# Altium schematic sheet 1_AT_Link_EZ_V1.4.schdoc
size 309 x 223 mm; Symbol: Artery_A4; Device: Artery_A4; Company: Artery Technology; Drawed: SD; Version: 1.0; Page Size: A4; @Project Name: AT-START-A403A V1.3; @Page Count: 5; @Update Date: 2023-11-22; @Schematic Name: AT_START_A403A; @Page No: 1; @Page Name: AT_Link_EZ_V1.4
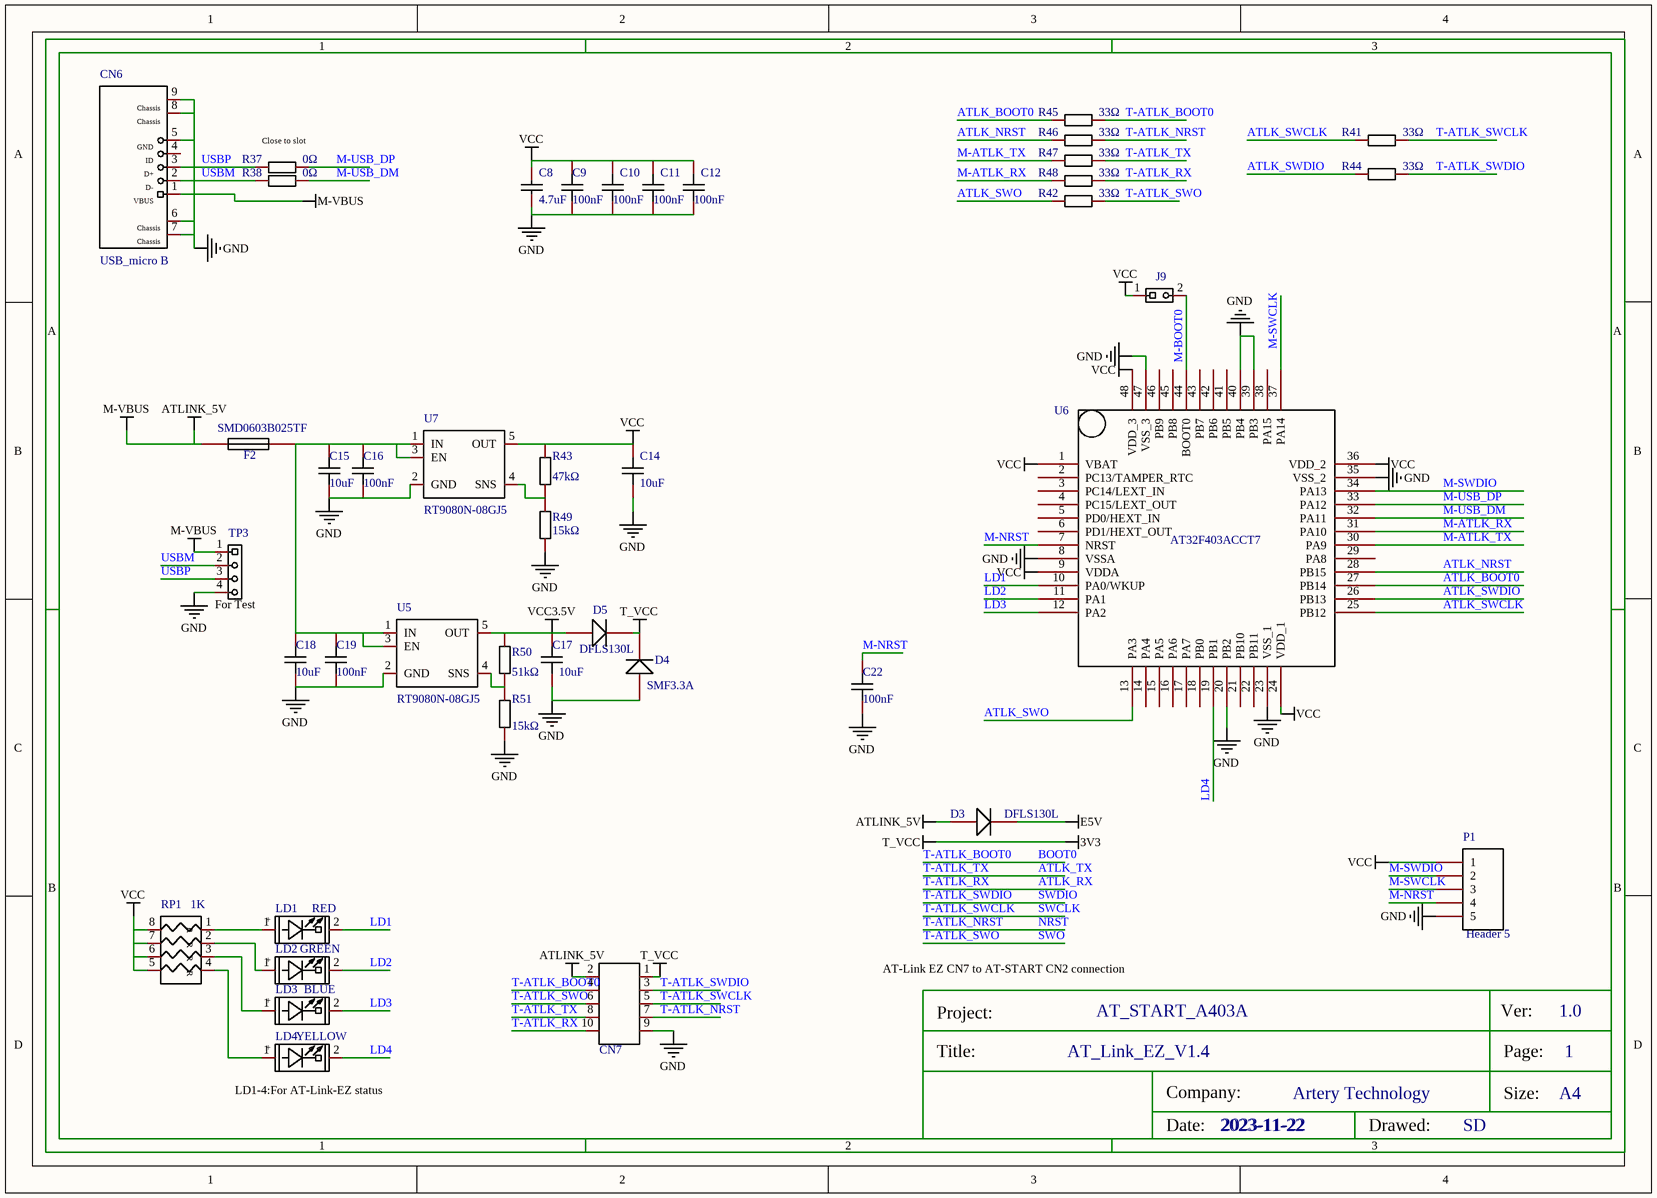
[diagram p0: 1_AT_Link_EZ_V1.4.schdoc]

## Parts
C8  value 4.7uF  [C0603]  (hidden comment: CL10A475KO8NNNC)
C9  value 100nF  [C0603]  (hidden comment: CC0603KRX7R9BB104)
C10  value 100nF  [C0603]  (hidden comment: CC0603KRX7R9BB104)
C11  value 100nF  [C0603]  (hidden comment: CC0603KRX7R9BB104)
C12  value 100nF  [C0603]  (hidden comment: CC0603KRX7R9BB104)
C14  value 10uF  [C0603]  (hidden comment: CL10A106MA8NRNC)
C15  value 10uF  [C0603]  (hidden comment: CL10A106MA8NRNC)
C16  value 100nF  [C0603]  (hidden comment: CC0603KRX7R9BB104)
C17  value 10uF  [C0603]  (hidden comment: CL10A106MA8NRNC)
C18  value 10uF  [C0603]  (hidden comment: CL10A106MA8NRNC)
C19  value 100nF  [C0603]  (hidden comment: CC0603KRX7R9BB104)
C22  value 100nF  [C0603]  (hidden comment: CC0603KRX7R9BB104)
CN6  USB_micro B  [USB_MIC_DIP]
CN7  CON1  [HDR2X5]  (value not drawn)
D3  DFLS130L  [SOD-123]
D4  SMF3.3A  [SOD-123]
D5  DFLS130L  [SOD-123]
F2  SMD0603B025TF  [R0603]
J9  1X2P_2.54M  [HDR1X2]  (value not drawn)
LD1  RED  [LED0603]
LD2  GREEN  [LED0603]
LD3  BLUE  [LED0603]
LD4  YELLOW  [LED0603]
P1  Header 5  [HDR1X5]
R37  0Ω  [R0603]
R38  0Ω  [R0603]
R41  value 33Ω  [R0603]  (hidden comment: 0603WAF330JT5E)
R42  value 33Ω  [R0603]  (hidden comment: 0603WAF330JT5E)
R43  value 47kΩ  [R0603]  (hidden comment: 0603WAF4702T5E)
R44  value 33Ω  [R0603]  (hidden comment: 0603WAF330JT5E)
R45  value 33Ω  [R0603]  (hidden comment: 0603WAF330JT5E)
R46  value 33Ω  [R0603]  (hidden comment: 0603WAF330JT5E)
R47  value 33Ω  [R0603]  (hidden comment: 0603WAF330JT5E)
R48  value 33Ω  [R0603]  (hidden comment: 0603WAF330JT5E)
R49  value 15kΩ  [R0603]  (hidden comment: 0603WAF1502T5E)
R50  value 51kΩ  [R0603]  (hidden comment: 0603WAF5102T5E)
R51  value 15kΩ  [R0603]  (hidden comment: 0603WAF1502T5E)
RP1  1K  [RP_4-0603]
TP3  1X4P_2.54F  [HDR1X4 - TOP]  (value not drawn)
U5  RT9080N-08GJ5  [SOT-23-5]
U6  AT32F403ACCT7  [LQFP-48_L7.0-W7.0-P0.50-LS9.0-BL]
U7  RT9080N-08GJ5  [SOT-23-5]

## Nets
3V3: CN7.1 D4.2(K) D5.2(K)  [also labelled T_VCC]
ATLINK_5V: CN6.1(VBUS) CN7.2 D3.1(A) F2.1 TP3.1  [also labelled M-VBUS]
E5V: D3.2(K)
GND: C8.1 C9.1 C10.1 C11.1 C12.1 C14.1 C15.1 C16.1 C17.1 C18.1 C19.1 C22.1 CN6.5(GND) CN6.6 CN6.7 CN6.8 CN6.9 CN7.9 D4.1(A) P1.5 R49.2 R51.2 TP3.4 U5.2(GND) U6.8(VSSA) U6.20(PB2) U6.23(VSS_1) U6.35(VSS_2) U6.39(PB3) U6.40(PB4) U6.47(VSS_3) U7.2(GND)
VCC: C8.2 C9.2 C10.2 C11.2 C12.2 C14.2 J9.1 P1.1 R43.1 RP1.5 RP1.6 RP1.7 RP1.8 U6.1(VBAT) U6.9(VDDA) U6.24(VDD_1) U6.36(VDD_2) U6.48(VDD_3) U7.5(OUT)
VCC3.5V: C17.2 D5.1(A) R50.1 U5.5(OUT)
ATLK_BOOT0: R45.1 U6.27(PB14)
ATLK_NRST: R46.1 U6.28(PB15)
ATLK_RX: CN7.10 R48.2  [also labelled T-ATLK_RX]
ATLK_SWCLK: R41.1 U6.25(PB12)
ATLK_SWDIO: R44.1 U6.26(PB13)
ATLK_SWO: R42.1 U6.13(PA3)
ATLK_TX: CN7.8 R47.2  [also labelled T-ATLK_TX]
BOOT0: CN7.4 R45.2  [also labelled T-ATLK_BOOT0]
LD1: LD1.2(CATHODE) U6.10(PA0/WKUP)
LD2: LD2.2(CATHODE) U6.11(PA1)
LD3: LD3.2(CATHODE) U6.12(PA2)
LD4: LD4.2(CATHODE) U6.19(PB1)
M-ATLK_RX: R48.1 U6.31(PA10)
M-ATLK_TX: R47.1 U6.30(PA9)
M-BOOT0: J9.2 U6.44(BOOT0)
M-NRST: C22.2 P1.4 U6.7(NRST)
M-SWCLK: P1.3 U6.37(PA14)
M-SWDIO: P1.2 U6.34(PA13)
M-USB_DM: R38.1 U6.32(PA11)
M-USB_DP: R37.1 U6.33(PA12)
NRST: CN7.7 R46.2  [also labelled T-ATLK_NRST]
SWCLK: CN7.5 R41.2  [also labelled T-ATLK_SWCLK]
SWDIO: CN7.3 R44.2  [also labelled T-ATLK_SWDIO]
SWO: CN7.6 R42.2  [also labelled T-ATLK_SWO]
USBM: CN6.2(D-) R38.2 TP3.2
USBP: CN6.3(D+) R37.2 TP3.3
NetC15_2: C15.2 C16.2 C18.2 C19.2 F2.2 U5.1(IN) U5.3(EN) U7.1(IN) U7.3(EN)
NetLD1_1: LD1.1(ANODE) RP1.1
NetLD2_1: LD2.1(ANODE) RP1.2
NetLD3_1: LD3.1(ANODE) RP1.3
NetLD4_1: LD4.1(ANODE) RP1.4
NetR43_2: R43.2 R49.1 U7.4(SNS)
NetR50_2: R50.2 R51.1 U5.4(SNS)

Not connected (* = marked no-connect by the designer): CN6 4(ID); U6 2(PC13/TAMPER_RTC) 3(PC14/LEXT_IN) 4(PC15/LEXT_OUT) 5(PD0/HEXT_IN) 6(PD1/HEXT_OUT) 14(PA4) 15(PA5) 16(PA6) 17(PA7) 18(PB0) 21(PB10) 22(PB11) 29(PA8) 38(PA15) 41(PB5) 42(PB6) 43(PB7) 45(PB8) 46(PB9)

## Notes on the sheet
- Close to slot
- (near TP3) For Test
- AT-Link EZ CN7 to AT-START CN2 connection
- (near LD4) LD1-4:For AT-Link-EZ status
- 2023-11-22

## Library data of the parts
C8 = CL10A475KO8NNNC: 容值:4.7uF;精度:±10%;额定电压:16V;材质(温度系数):X5R;; Manufacturer: SAMSUNG(三星); Add into BOM: yes; Tolerance: ±10%; Voltage Rated: 16V; Temperature Coefficient: X5R
C9-C12 C16 C19 C22 = CC0603KRX7R9BB104: 容值:100nF;精度:±10%;额定电压:50V;材质(温度系数):X7R;; Manufacturer: YAGEO(国巨); Add into BOM: yes; Tolerance: ±10%; Voltage Rated: 50V; Temperature Coefficient: X7R
C14 C15 C17 C18 = CL10A106MA8NRNC: 容值:10uF;精度:±20%;额定电压:25V;材质(温度系数):X5R;; Manufacturer: SAMSUNG(三星); Add into BOM: yes; Tolerance: ±20%; Voltage Rated: 25V; Temperature Coefficient: X5R
CN6 = USB_micro B: Symbol: USB_miniAB,SMD_0; Add into BOM: yes
CN7 = CON1: Symbol: CON10A_0; Add into BOM: yes
D3 D5 = DFLS130L: Default Diode; Add into BOM: yes
D4 = SMF3.3A: Default Diode; Add into BOM: yes
F2 = SMD0603B025TF: Fuse; Symbol: Fuse 1; Add into BOM: yes
J9 = 1X2P_2.54M: Symbol: 1X2P,Male,DIP_2.54; Origin Footprint 2: SIP_2P; Add into BOM: yes
LD1 = RED: Symbol: RED,SMD0603; Add into BOM: yes
LD2 = GREEN: Symbol: GREEN,SMD0603; Add into BOM: yes
LD3 = BLUE: ?--LED ?-- 0603; Symbol: BLUE,SMD0603; Add into BOM: yes
LD4 = YELLOW: Symbol: YELLOW,SMD0603; Add into BOM: yes
P1 = Header 5: Header, 5-Pin; Add into BOM: yes
R37 R38 = 0603WAF220JT5E: 电阻类型:厚膜电阻;阻值:22Ω;精度:±1%;功率:100mW;温度系数:±100ppm/℃;最大工作电压:75V;工作温度范围:-55℃~+155℃;; Manufacturer: UNI-ROYAL(厚声); Add into BOM: yes; Tolerance: ±1%; Power(Watts): 100mW; Overload Voltage (Max): 75V
R41 R42 R44-R48 = 0603WAF330JT5E: 电阻类型:厚膜电阻;阻值:33Ω;精度:±1%;功率:100mW;温度系数:±100ppm/℃;最大工作电压:75V;工作温度范围:-55℃~+155℃;; Manufacturer: UNI-ROYAL(厚声); Add into BOM: yes; Tolerance: ±1%; Power(Watts): 100mW; Overload Voltage (Max): 75V
R43 = 0603WAF4702T5E: 电阻类型:厚膜电阻;阻值:47kΩ;精度:±1%;功率:100mW;温度系数:±100ppm/℃;最大工作电压:75V;工作温度范围:-55℃~+155℃;; Manufacturer: UNI-ROYAL(厚声); Add into BOM: yes; Tolerance: ±1%; Power(Watts): 100mW; Overload Voltage (Max): 75V
R49 R51 = 0603WAF1502T5E: 电阻类型:厚膜电阻;阻值:15kΩ;精度:±1%;功率:100mW;温度系数:±100ppm/℃;最大工作电压:75V;工作温度范围:-55℃~+155℃;; Manufacturer: UNI-ROYAL(厚声); Add into BOM: yes; Tolerance: ±1%; Power(Watts): 100mW; Overload Voltage (Max): 75V
R50 = 0603WAF5102T5E: 电阻类型:厚膜电阻;阻值:51kΩ;精度:±1%;功率:100mW;温度系数:±100ppm/℃;最大工作电压:75V;工作温度范围:-55℃~+155℃;; Manufacturer: UNI-ROYAL(厚声); Add into BOM: yes; Tolerance: ±1%; Power(Watts): 100mW; Overload Voltage (Max): 75V
RP1 = 1K: Symbol: 22,1/16W,5%,8P4R; Add into BOM: yes
TP3 = 1X4P_2.54F: Symbol: 1X4P,Female,DIP_2.54; Origin Footprint 2: SIP_4P; Add into BOM: yes
U5 U7 = RT9080N-08GJ5: Add into BOM: yes
U6 = AT32F403ACCT7: 频率 (MHz)：240，FLASH (KB)：256，SRAM (KB)：224，CPU：ARM? Cortex?-M4，工作电压（V）：2.6~3.6，工作温度：-40°C ~ 105°C，封装：LQFP48; Manufacturer: ARTERY（雅特力）; Symbol: LQFP48&QFN48; Add into BOM: yes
